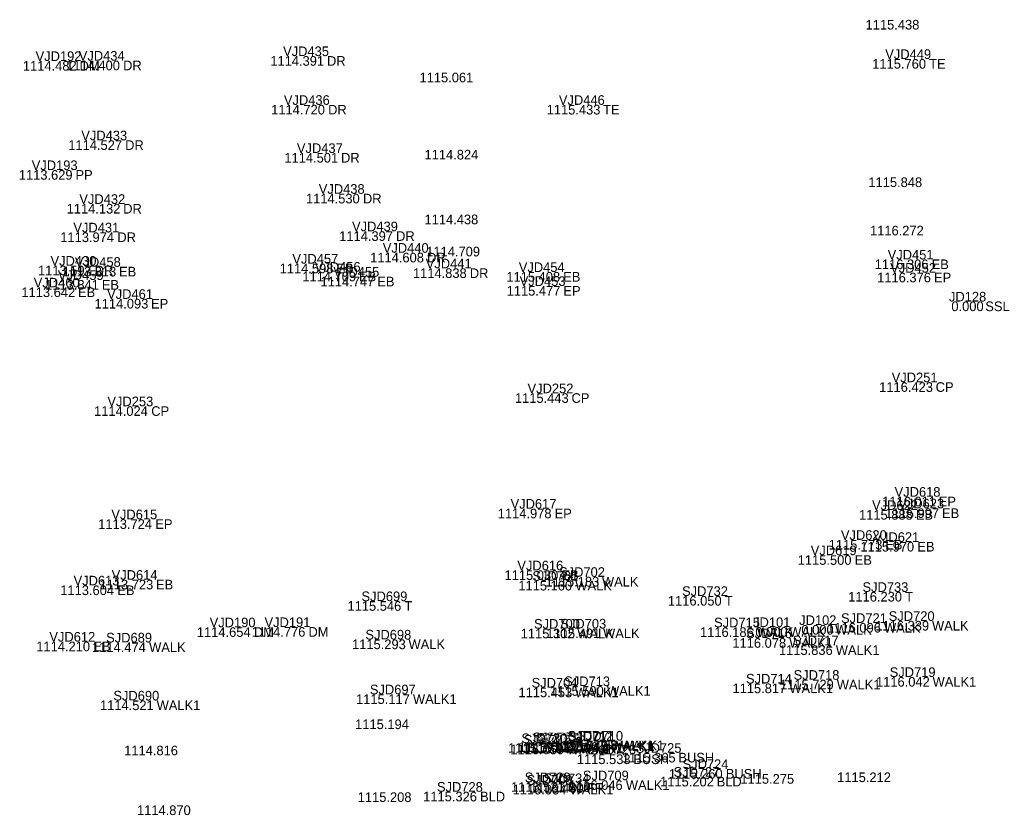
# Model space of a CAD drawing. Extents: x 1629927 to 1630657, y 484405 to 484576.
# Drawn here: x 1630554.7 to 1630657.3, y 484456 to 484538.6 of the extents above; entities that cross this region are included whole.
import ezdxf

# ---------------------------------------------------------------- set-up
doc = ezdxf.new("R2010")
doc.units = 0
for name, color, linetype in [('SV_X_Text_Comment', 7, 'Continuous'), ('SV_X_Text_Elevation', 7, 'Continuous'), ('SV_X_Text_Name', 7, 'Continuous')]:
    doc.layers.add(name, color=color, linetype=linetype)

msp = doc.modelspace()

# ---------------------------------------------------------------- texts
at = {"layer": 'SV_X_Text_Comment'}
for s, p in [('DM', (1630560.89, 484533.31)), ('DR', (1630565.41, 484533.35)), ('DR', (1630586.56, 484533.82)), ('TE', (1630649.04, 484533.52)), ('DR', (1630586.68, 484528.76)), ('TE', (1630615.21, 484528.76)), ('DR', (1630565.62, 484525.08)), ('DR', (1630588.02, 484523.77)), ('PP', (1630560.47, 484521.99)), ('DR', (1630590.29, 484519.53)), ('DR', (1630565.42, 484518.48)), ('DR', (1630564.81, 484515.52)), ('DR', (1630593.73, 484515.64)), ('DR', (1630596.94, 484513.41)), ('EB', (1630649.29, 484512.71)), ('DR', (1630562.47, 484512.07)), ('EB', (1630564.99, 484511.95)), ('EB', (1630587.54, 484512.28)), ('DR', (1630601.38, 484511.79)), ('EB', (1630589.88, 484511.44)), ('EB', (1630591.78, 484510.92)), ('EB', (1630611.07, 484511.41)), ('EP', (1630649.54, 484511.34)), ('EB', (1630560.73, 484509.81)), ('EB', (1630563.2, 484510.58)), ('EP', (1630611.09, 484509.96)), ('EP', (1630568.31, 484508.62)), ('SSL', (1630654.86, 484508.35)), ('CP', (1630649.71, 484499.97)), ('CP', (1630611.93, 484498.83)), ('CP', (1630568.33, 484497.48)), ('EP', (1630650.03, 484488.09)), ('EP', (1630610.18, 484486.85)), ('EB', (1630647.66, 484486.71)), ('EB', (1630650.37, 484486.88)), ('EP', (1630568.75, 484485.75)), ('EB', (1630644.48, 484483.61)), ('EB', (1630647.81, 484483.4)), ('EB', (1630641.31, 484482.02)), ('EB', (1630610.89, 484480.45)), ('EB', (1630564.81, 484478.88)), ('EB', (1630568.82, 484479.47)), ('WALK', (1630612.33, 484479.36)), ('WALK', (1630615.09, 484479.77)), ('T', (1630627.84, 484477.79)), ('T', (1630646.55, 484478.21)), ('T', (1630594.59, 484477.25)), ('WALK', (1630639.29, 484474.78)), ('WALK', (1630644.35, 484474.99)), ('WALK', (1630649.33, 484475.2)), ('DM', (1630578.98, 484474.54)), ('DM', (1630584.64, 484474.56)), ('WALK', (1630612.53, 484474.39)), ('WALK', (1630615.21, 484474.41)), ('WALK', (1630631.16, 484474.53)), ('WALK', (1630634.52, 484474.56)), ('EB', (1630562.32, 484473.05)), ('WALK', (1630568.11, 484472.96)), ('WALK', (1630595.02, 484473.27)), ('WALK1', (1630634.52, 484473.41)), ('WALK1', (1630639.35, 484472.67)), ('WALK1', (1630634.53, 484468.7)), ('WALK1', (1630639.45, 484469.09)), ('WALK1', (1630649.39, 484469.38)), ('WALK1', (1630595.48, 484467.58)), ('WALK1', (1630612.29, 484468.28)), ('WALK1', (1630615.61, 484468.43)), ('WALK1', (1630568.89, 484466.94)), ('B10', (1630611.21, 484462.51)), ('B10', (1630612.34, 484462.61)), ('WALK1', (1630612.76, 484462.55)), ('WALK1', (1630612.78, 484462.44)), ('WALK1', (1630615.97, 484462.78)), ('WALK1', (1630616.02, 484462.69)), ('WALK1', (1630617.01, 484462.77)), ('WALK1', (1630611.46, 484462.36)), ('BUSH', (1630623.02, 484461.51)), ('BUSH', (1630618.34, 484461.34)), ('BUSH', (1630627.94, 484459.83)), ('B10', (1630611.53, 484458.46)), ('FF', (1630613.53, 484458.36)), ('WALK1', (1630617.57, 484458.66)), ('BLD', (1630626.99, 484459.02)), ('BLD', (1630602.44, 484457.47)), ('WALK1', (1630611.74, 484458.19))]:
    msp.add_text(s, height=1, dxfattribs=at).set_placement(p)
at = {"layer": 'SV_X_Text_Elevation'}
for s, p in [('1115.438', (1630642.44, 484537.58)), ('1114.482', (1630555.01, 484533.31)), ('1114.400', (1630559.5, 484533.35)), ('1114.391', (1630580.68, 484533.82)), ('1115.760', (1630643.13, 484533.52)), ('1115.061', (1630596.16, 484532.1)), ('1114.720', (1630580.77, 484528.76)), ('1115.433', (1630609.35, 484528.76)), ('1114.527', (1630559.72, 484525.08)), ('1114.824', (1630596.68, 484524.09)), ('1114.501', (1630582.14, 484523.77)), ('1113.629', (1630554.59, 484521.99)), ('1115.848', (1630642.73, 484521.23)), ('1114.530', (1630584.38, 484519.53)), ('1114.132', (1630559.55, 484518.48)), ('1114.438', (1630596.68, 484517.37)), ('1116.272', (1630642.9, 484516.21)), ('1113.974', (1630558.89, 484515.52)), ('1114.397', (1630587.83, 484515.64)), ('1114.709', (1630596.86, 484514.03)), ('1114.608', (1630591.04, 484513.41)), ('1116.306', (1630643.39, 484512.71)), ('1113.597', (1630556.58, 484512.07)), ('1113.813', (1630559.12, 484511.95)), ('1114.598', (1630581.65, 484512.28)), ('1114.838', (1630595.48, 484511.79)), ('1114.709', (1630584, 484511.44)), ('1114.747', (1630585.89, 484510.92)), ('1115.408', (1630605.17, 484511.41)), ('1116.376', (1630643.64, 484511.34)), ('1113.642', (1630554.86, 484509.81)), ('1113.841', (1630557.32, 484510.58)), ('1115.477', (1630605.2, 484509.96)), ('1114.093', (1630562.45, 484508.62)), ('0.000', (1630651.34, 484508.35)), ('1116.423', (1630643.85, 484499.97)), ('1115.443', (1630606.06, 484498.83)), ('1114.024', (1630562.4, 484497.48)), ('1116.011', (1630644.16, 484488.09)), ('1114.978', (1630604.28, 484486.85)), ('1115.888', (1630641.76, 484486.71)), ('1115.997', (1630644.48, 484486.88)), ('1113.724', (1630562.83, 484485.75)), ('1115.773', (1630638.61, 484483.61)), ('1115.970', (1630641.9, 484483.4)), ('1115.500', (1630635.4, 484482.02)), ('1115.030', (1630604.98, 484480.45)), ('1113.604', (1630558.89, 484478.88)), ('1113.723', (1630562.96, 484479.47)), ('1115.160', (1630606.41, 484479.36)), ('1115.183', (1630609.23, 484479.77)), ('1116.050', (1630621.93, 484477.79)), ('1116.230', (1630640.64, 484478.21)), ('1115.546', (1630588.69, 484477.25)), ('0.000', (1630635.78, 484474.78)), ('1116.096', (1630638.45, 484474.99)), ('1116.339', (1630643.45, 484475.2)), ('1114.654', (1630573.06, 484474.54)), ('1114.776', (1630578.74, 484474.56)), ('1115.302', (1630606.66, 484474.39)), ('1115.491', (1630609.33, 484474.41)), ('1116.186', (1630625.26, 484474.53)), ('0.000', (1630631, 484474.56)), ('1114.210', (1630556.4, 484473.05)), ('1114.474', (1630562.19, 484472.96)), ('1115.293', (1630589.16, 484473.27)), ('1116.078', (1630628.62, 484473.41)), ('1115.836', (1630633.45, 484472.67)), ('1115.817', (1630628.63, 484468.7)), ('1115.729', (1630633.56, 484469.09)), ('1116.042', (1630643.52, 484469.38)), ('1115.117', (1630589.58, 484467.58)), ('1115.453', (1630606.43, 484468.28)), ('1115.590', (1630609.7, 484468.43)), ('1114.521', (1630563.01, 484466.94)), ('1115.194', (1630589.48, 484464.97)), ('1115.383', (1630605.35, 484462.51)), ('1115.517', (1630606.44, 484462.61)), ('1115.622', (1630606.89, 484462.55)), ('1116.043', (1630606.92, 484462.44)), ('1115.773', (1630610.11, 484462.78)), ('1116.043', (1630610.16, 484462.69)), ('1116.063', (1630611.15, 484462.77)), ('1114.816', (1630565.52, 484462.25)), ('1116.059', (1630605.58, 484462.36)), ('1115.365', (1630617.15, 484461.51)), ('1115.533', (1630612.48, 484461.34)), ('1115.260', (1630622.03, 484459.83)), ('1115.275', (1630629.45, 484459.3)), ('1115.212', (1630639.49, 484459.47)), ('1115.521', (1630605.65, 484458.46)), ('1116.480', (1630607.62, 484458.36)), ('1116.046', (1630611.66, 484458.66)), ('1115.202', (1630621.12, 484459.02)), ('1115.208', (1630589.75, 484457.41)), ('1115.326', (1630596.54, 484457.47)), ('1116.034', (1630605.82, 484458.19)), ('1114.870', (1630566.85, 484456.05))]:
    msp.add_text(s, height=1, dxfattribs=at).set_placement(p)
at = {"layer": 'SV_X_Text_Name'}
for s, p in [('VJD192', (1630556.33, 484534.31)), ('VJD434', (1630560.81, 484534.35)), ('VJD435', (1630582.01, 484534.82)), ('VJD449', (1630644.48, 484534.52)), ('VJD436', (1630582.09, 484529.76)), ('VJD446', (1630610.62, 484529.76)), ('VJD433', (1630561.07, 484526.08)), ('VJD437', (1630583.44, 484524.77)), ('VJD193', (1630555.93, 484522.99)), ('VJD438', (1630585.71, 484520.53)), ('VJD432', (1630560.87, 484519.48)), ('VJD431', (1630560.25, 484516.52)), ('VJD439', (1630589.16, 484516.64)), ('VJD440', (1630592.35, 484514.41)), ('VJD451', (1630644.73, 484513.71)), ('VJD430', (1630557.88, 484513.07)), ('VJD458', (1630560.41, 484512.95)), ('VJD457', (1630582.97, 484513.28)), ('VJD441', (1630596.81, 484512.79)), ('VJD456', (1630585.29, 484512.44)), ('VJD455', (1630587.23, 484511.92)), ('VJD454', (1630606.46, 484512.41)), ('VJD452', (1630644.99, 484512.34)), ('VJD460', (1630556.14, 484510.81)), ('VJD459', (1630558.64, 484511.58)), ('VJD453', (1630606.55, 484510.96)), ('VJD461', (1630563.75, 484509.62)), ('JD128', (1630651.09, 484509.35)), ('VJD251', (1630645.15, 484500.97)), ('VJD252', (1630607.37, 484499.83)), ('VJD253', (1630563.78, 484498.48)), ('VJD618', (1630645.45, 484489.09)), ('VJD617', (1630605.61, 484487.85)), ('VJD622', (1630643.11, 484487.71)), ('VJD623', (1630645.83, 484487.88)), ('VJD615', (1630564.19, 484486.75)), ('VJD620', (1630639.88, 484484.61)), ('VJD621', (1630643.25, 484484.4)), ('VJD619', (1630636.75, 484483.02)), ('VJD616', (1630606.31, 484481.45)), ('VJD613', (1630560.27, 484479.88)), ('VJD614', (1630564.22, 484480.47)), ('SJD701', (1630607.87, 484480.36)), ('SJD702', (1630610.64, 484480.77)), ('SJD733', (1630642.12, 484479.21)), ('SJD699', (1630590.14, 484478.25)), ('SJD732', (1630623.4, 484478.79)), ('JD102', (1630635.55, 484475.78)), ('SJD721', (1630639.89, 484475.99)), ('SJD720', (1630644.84, 484476.2)), ('VJD190', (1630574.39, 484475.54)), ('VJD191', (1630580.08, 484475.56)), ('SJD700', (1630608.04, 484475.39)), ('SJD703', (1630610.77, 484475.41)), ('SJD715', (1630626.72, 484475.53)), ('JD101', (1630630.77, 484475.56)), ('VJD612', (1630557.76, 484474.05)), ('SJD689', (1630563.65, 484473.96)), ('SJD698', (1630590.55, 484474.27)), ('SJD716', (1630630.04, 484474.41)), ('SJD717', (1630634.88, 484473.67)), ('SJD714', (1630630.03, 484469.7)), ('SJD718', (1630634.97, 484470.09)), ('SJD719', (1630644.94, 484470.38)), ('SJD697', (1630591.01, 484468.58)), ('SJD704', (1630607.79, 484469.28)), ('SJD713', (1630611.17, 484469.43)), ('SJD690', (1630564.4, 484467.94)), ('SJD730', (1630606.73, 484463.51)), ('SJD731', (1630607.88, 484463.61)), ('SJD706', (1630608.3, 484463.44)), ('SJD705', (1630608.31, 484463.55)), ('SJD712', (1630611.52, 484463.78)), ('SJD711', (1630611.57, 484463.69)), ('SJD710', (1630612.52, 484463.77)), ('SJD707', (1630606.99, 484463.36)), ('SJD725', (1630618.58, 484462.51)), ('SJD726', (1630613.86, 484462.34)), ('SJD724', (1630623.45, 484460.83)), ('SJD729', (1630607.08, 484459.46)), ('SJD734', (1630609.03, 484459.36)), ('SJD709', (1630613.11, 484459.66)), ('SJD727', (1630622.52, 484460.02)), ('SJD728', (1630597.97, 484458.47)), ('SJD708', (1630607.27, 484459.19))]:
    msp.add_text(s, height=1, dxfattribs=at).set_placement(p)

doc.saveas('drawing.dxf')
